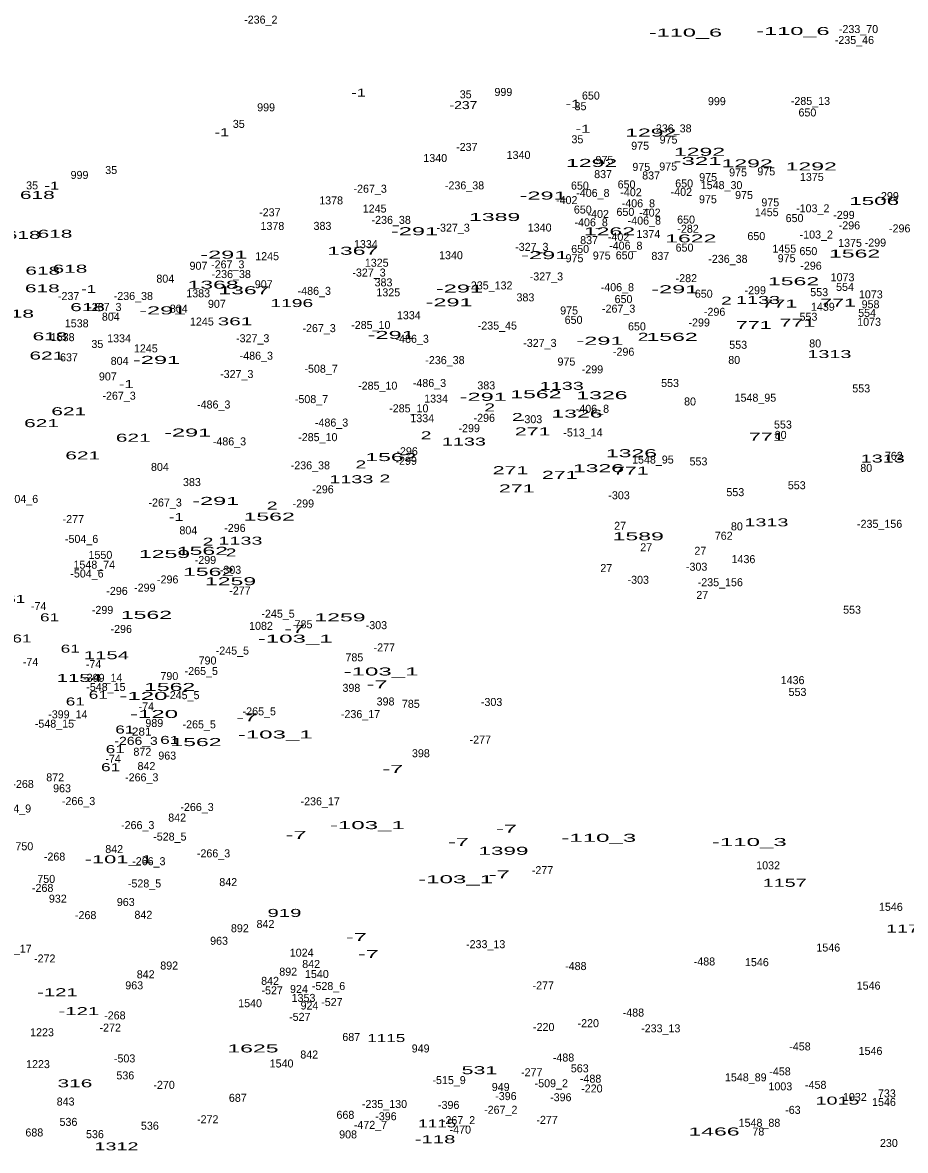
# Model space of a CAD drawing. Extents: x -660434 to -656144, y -997850 to -994016.
# Drawn here: x -658131 to -657690, y -996650 to -996086 of the extents above; entities that cross this region are included whole.
import ezdxf
from ezdxf.enums import TextEntityAlignment as Align

# ---------------------------------------------------------------- set-up
doc = ezdxf.new("R2010")
doc.units = 0
doc.header["$LTSCALE"] = 1.6
doc.layers.add('24', color=7, linetype='Continuous')

msp = doc.modelspace()

# ---------------------------------------------------------------- texts
at = {"layer": '24'}
for s, p in [('-236_2', (-658012.228, -996086.57)), ('-233_70', (-657713.311, -996091.3)), ('-235_46', (-657715.371, -996096.78)), ('35', (-657909.757, -996123.92)), ('999', (-657890.913, -996122.74)), ('650', (-657847.157, -996124.54)), ('999', (-658009.573, -996130.42)), ('35', (-657852.347, -996129.88)), ('999', (-657784.153, -996127.35)), ('-285_13', (-657737.355, -996127.24)), ('650', (-657738.867, -996132.99)), ('35', (-658023.237, -996138.71)), ('-236_38', (-657806.607, -996140.95)), ('35', (-657853.887, -996146.4)), ('975', (-657808.308, -996146.56)), ('-237', (-657909.211, -996150.24)), ('1340', (-657883.328, -996154.22)), ('975', (-657822.518, -996149.64)), ('1340', (-657924.988, -996155.76)), ('975', (-657840.378, -996156.74)), ('975', (-657821.938, -996160.2)), ('975', (-657808.498, -996160.01)), ('999', (-658102.883, -996164.23)), ('35', (-658087.047, -996161.76)), ('837', (-657841.043, -996163.82)), ('837', (-657817.033, -996164.49)), ('975', (-657788.518, -996165.33)), ('975', (-657773.548, -996162.93)), ('975', (-657759.428, -996162.45)), ('1375', (-657736.656, -996165.23)), ('35', (-658126.597, -996169.45)), ('-267_3', (-657957.534, -996171.12)), ('-236_38', (-657910.337, -996169.45)), ('650', (-657852.637, -996169.54)), ('650', (-657829.307, -996168.96)), ('650', (-657800.507, -996168.48)), ('1548_30', (-657781.796, -996169.31)), ('1378', (-657977.056, -996176.96)), ('-402', (-657859.223, -996176.81)), ('-406_8', (-657846.156, -996173.23)), ('-402', (-657827.083, -996172.88)), ('-402', (-657801.903, -996172.68)), ('975', (-657788.618, -996176.38)), ('975', (-657770.568, -996174.27)), ('-299', (-657698.515, -996174.8)), ('1245', (-657955.294, -996181.03)), ('650', (-657851.197, -996181.54)), ('650', (-657829.877, -996182.7)), ('-406_8', (-657823.406, -996178.41)), ('975', (-657757.418, -996177.92)), ('-103_2', (-657736.19, -996180.93)), ('-237', (-658007.711, -996182.9)), ('-236_38', (-657947.017, -996186.7)), ('-406_8', (-657847.026, -996187.92)), ('-402', (-657843.473, -996183.73)), ('-406_8', (-657820.426, -996187.06)), ('-402', (-657817.653, -996183.06)), ('650', (-657799.547, -996186.54)), ('1455', (-657759.204, -996182.84)), ('650', (-657745.297, -996185.81)), ('-299', (-657720.605, -996184.21)), ('1378', (-658006.426, -996189.73)), ('383', (-657981.387, -996189.7)), ('-327_3', (-657916.048, -996190.59)), ('1340', (-657872.758, -996190.52)), ('1374', (-657818.4, -996193.75)), ('-282', (-657798.555, -996191.13)), ('-103_2', (-657734.44, -996194.02)), ('-296', (-657717.865, -996189.43)), ('-296', (-657692.705, -996190.95)), ('1334', (-657959.694, -996198.83)), ('837', (-657848.043, -996196.82)), ('-402', (-657833.303, -996195.16)), ('-406_8', (-657829.696, -996199.59)), ('650', (-657764.407, -996194.8)), ('1375', (-657717.546, -996198.17)), ('-299', (-657704.865, -996198.04)), ('1245', (-658009.054, -996204.84)), ('1340', (-657917.118, -996204.35)), ('-327_3', (-657876.688, -996200.18)), ('650', (-657852.527, -996201.23)), ('975', (-657841.718, -996204.52)), ('650', (-657830.267, -996204.4)), ('837', (-657812.433, -996204.7)), ('650', (-657800.307, -996200.56)), ('1455', (-657750.394, -996201.06)), ('650', (-657738.387, -996202.33)), ('907', (-658043.402, -996209.64)), ('-267_3', (-658028.764, -996208.94)), ('1325', (-657954.25, -996208.12)), ('975', (-657855.348, -996205.86)), ('-236_38', (-657778.627, -996206.18)), ('975', (-657749.258, -996205.86)), ('-296', (-657737.065, -996209.6)), ('804', (-658059.985, -996216.08)), ('-236_38', (-658027.007, -996213.78)), ('-327_3', (-657958.098, -996213.02)), ('-327_3', (-657869.398, -996214.97)), ('-282', (-657799.415, -996215.82)), ('1073', (-657721.28, -996215.37)), ('907', (-658010.762, -996218.86)), ('-486_3', (-657985.472, -996222.18)), ('383', (-657950.857, -996217.94)), ('-235_132', (-657897.665, -996219.45)), ('-406_8', (-657833.916, -996220.34)), ('-299', (-657764.955, -996221.86)), ('554', (-657720.061, -996220.2)), ('-237', (-658108.321, -996224.77)), ('-236_38', (-658075.967, -996224.73)), ('1383', (-658043.55, -996223.42)), ('1325', (-657948.48, -996222.92)), ('383', (-657879.887, -996225.43)), ('650', (-657830.837, -996226.3)), ('650', (-657790.707, -996223.61)), ('553', (-657732.967, -996222.82)), ('1073', (-657707.16, -996223.92)), ('-267_3', (-658090.214, -996230.22)), ('804', (-658053.265, -996231.06)), ('907', (-658034.192, -996228.66)), ('975', (-657858.038, -996231.98)), ('-267_3', (-657833.264, -996231.07)), ('-296', (-657785.265, -996232.64)), ('1439', (-657731.15, -996230.13)), ('554', (-657709.021, -996233.17)), ('958', (-657707.283, -996228.87)), ('1538', (-658104.29, -996238.4)), ('804', (-658087.245, -996235.1)), ('1245', (-658041.694, -996237.5)), ('-285_10', (-657957.219, -996239.23)), ('1334', (-657938.194, -996234.36)), ('650', (-657855.797, -996236.67)), ('-299', (-657792.995, -996237.99)), ('553', (-657738.347, -996235.12)), ('1073', (-657708.02, -996237.66)), ('-267_3', (-657983.074, -996240.82)), ('-235_45', (-657893.926, -996239.52)), ('650', (-657824.117, -996239.93)), ('1538', (-658111.3, -996245.32)), ('35', (-658093.957, -996248.72)), ('1334', (-658083.104, -996245.89)), ('-327_3', (-658016.278, -996245.86)), ('-486_3', (-657936.512, -996246.14)), ('-327_3', (-657872.648, -996248.21)), ('553', (-657773.477, -996249.14)), ('80', (-657734.971, -996248.46)), ('637', (-658108.158, -996255.39)), ('1245', (-658069.724, -996250.94)), ('-486_3', (-658014.462, -996254.6)), ('-296', (-657830.765, -996252.62)), ('804', (-658082.835, -996257.19)), ('-508_7', (-657982.072, -996261.11)), ('-236_38', (-657920.127, -996256.8)), ('975', (-657859.378, -996257.53)), ('-299', (-657846.375, -996261.42)), ('80', (-657775.481, -996256.72)), ('907', (-658088.722, -996264.96)), ('-327_3', (-658024.248, -996263.76)), ('-285_10', (-657953.759, -996269.57)), ('-486_3', (-657927.872, -996268.23)), ('383', (-657899.467, -996269.42)), ('553', (-657807.557, -996268.25)), ('553', (-657711.947, -996270.94)), ('-267_3', (-658083.104, -996274.59)), ('-508_7', (-657986.872, -996276.29)), ('1334', (-657924.564, -996276.04)), ('80', (-657797.571, -996277.47)), ('1548_95', (-657764.877, -996275.58)), ('-486_3', (-658035.772, -996278.99)), ('-285_10', (-657938.209, -996280.91)), ('-406_8', (-657846.396, -996281.14)), ('-486_3', (-657976.832, -996288.02)), ('1334', (-657931.474, -996285.84)), ('-296', (-657900.465, -996285.65)), ('-303', (-657876.839, -996286.33)), ('553', (-657751.107, -996289)), ('-285_10', (-657983.709, -996295.31)), ('-299', (-657908.005, -996290.82)), ('-513_14', (-657851.133, -996292.98)), ('80', (-657752.251, -996294.19)), ('-486_3', (-658027.902, -996297.43)), ('-296', (-657939.065, -996302.36)), ('1548_95', (-657816.137, -996306.51)), ('762', (-657695.668, -996304.65)), ('804', (-658062.675, -996310.2)), ('-236_38', (-657987.447, -996309.39)), ('-299', (-657939.495, -996307.14)), ('553', (-657793.357, -996307.44)), ('80', (-657709.431, -996310.7)), ('383', (-658046.667, -996317.77)), ('-296', (-657981.115, -996321.38)), ('553', (-657774.917, -996322.8)), ('553', (-657744.197, -996319.35)), ('-504_6', (-658131.886, -996326.2)), ('-267_3', (-658060.064, -996327.99)), ('-299', (-657990.945, -996328.46)), ('-303', (-657833.059, -996324.36)), ('-277', (-658105.975, -996336.26)), ('-296', (-658025.185, -996340.69)), ('27', (-657832.543, -996339.62)), ('80', (-657774.141, -996339.89)), ('-235_156', (-657702.751, -996338.64)), ('-504_6', (-658101.846, -996346.18)), ('804', (-658048.465, -996341.89)), ('762', (-657780.728, -996344.6)), ('27', (-657819.493, -996350.37)), ('1550', (-658092.434, -996354.16)), ('-299', (-658039.915, -996356.7)), ('27', (-657792.413, -996352.1)), ('1436', (-657770.85, -996356.29)), ('1548_74', (-658095.492, -996359.05)), ('-303', (-658027.369, -996361.63)), ('27', (-657839.453, -996360.75)), ('-303', (-657794.269, -996360.09)), ('-504_6', (-658099.156, -996363.47)), ('-296', (-658058.785, -996366.43)), ('-303', (-657823.459, -996366.62)), ('-235_156', (-657782.431, -996367.84)), ('-296', (-658084.135, -996372.19)), ('-299', (-658070.245, -996370.53)), ('-277', (-658022.645, -996371.99)), ('27', (-657791.453, -996374.19)), ('-74', (-658123.335, -996379.78)), ('-299', (-658091.365, -996381.67)), ('-245_5', (-658003.597, -996383.57)), ('553', (-657716.547, -996381.58)), ('-296', (-658082.015, -996391.2)), ('1082', (-658012.124, -996389.64)), ('785', (-657990.863, -996388.86)), ('-303', (-657954.409, -996389.29)), ('-245_5', (-658026.447, -996402.01)), ('-277', (-657950.445, -996400.42)), ('-74', (-658127.365, -996407.64)), ('790', (-658038.852, -996406.96)), ('785', (-657965.423, -996405.37)), ('-74', (-658095.875, -996408.79)), ('-265_5', (-658041.988, -996412.2)), ('-399_14', (-658091.25, -996415.63)), ('790', (-658057.952, -996414.74)), ('1436', (-657746.27, -996416.79)), ('-548_15', (-658089.699, -996420.2)), ('-245_5', (-658051.207, -996424.29)), ('398', (-657966.923, -996420.63)), ('553', (-657743.817, -996422.68)), ('-74', (-658069.485, -996429.92)), ('398', (-657949.833, -996427.45)), ('785', (-657937.203, -996428.62)), ('-303', (-657896.809, -996427.7)), ('-399_14', (-658108.73, -996433.88)), ('-265_5', (-658012.978, -996432.37)), ('-236_17', (-657962.366, -996433.76)), ('-548_15', (-658115.429, -996438.54)), ('989', (-658065.488, -996438.2)), ('-265_5', (-658043.028, -996438.89)), ('-277', (-657902.455, -996446.52)), ('872', (-658071.463, -996452.59)), ('398', (-657932.173, -996453.33)), ('-74', (-658086.085, -996456.04)), ('963', (-658059.018, -996454.5)), ('842', (-658069.411, -996459.75)), ('-268', (-658131.11, -996468.69)), ('872', (-658115.053, -996465.36)), ('-266_3', (-658071.773, -996465.37)), ('963', (-658111.628, -996470.84)), ('-504_9', (-658135.416, -996480.96)), ('-266_3', (-658103.353, -996477.25)), ('-266_3', (-658044.113, -996480.22)), ('-236_17', (-657982.526, -996477.36)), ('842', (-658054.051, -996485.49)), ('-266_3', (-658073.783, -996489.26)), ('-528_5', (-658057.702, -996494.99)), ('750', (-658130.477, -996499.83)), ('842', (-658085.541, -996501.24)), ('-266_3', (-658035.863, -996503.38)), ('-268', (-658115.36, -996504.99)), ('-266_3', (-658068.213, -996507.31)), ('1032', (-657758.534, -996509.37)), ('-277', (-657871.345, -996511.78)), ('-268', (-658121.31, -996520.66)), ('750', (-658119.527, -996516.15)), ('-528_5', (-658070.372, -996518.42)), ('842', (-658028.511, -996517.75)), ('932', (-658113.733, -996526.02)), ('963', (-658079.758, -996527.7)), ('1546', (-657697.12, -996530.11)), ('-268', (-658099.81, -996534.25)), ('842', (-658070.951, -996534.08)), ('892', (-658022.703, -996540.81)), ('842', (-658009.891, -996538.69)), ('963', (-658033.098, -996547.08)), ('-233_13', (-657899.765, -996548.78)), ('-548_17', (-658136.635, -996551.04)), ('1024', (-657991.788, -996553.02)), ('1546', (-657728.42, -996550.47)), ('-272', (-658120.271, -996555.93)), ('892', (-658058.033, -996559.45)), ('842', (-657987.041, -996558.67)), ('-488', (-657854.689, -996559.73)), ('-488', (-657790.369, -996557.43)), ('1546', (-657764.13, -996557.77)), ('842', (-658069.791, -996563.85)), ('892', (-657998.513, -996562.52)), ('1540', (-657984.178, -996563.68)), ('963', (-658075.528, -996569.36)), ('842', (-658007.591, -996567.12)), ('-527', (-658006.541, -996571.86)), ('924', (-657993.147, -996571.18)), ('-528_6', (-657978.348, -996569.7)), ('-277', (-657870.965, -996569.4)), ('1546', (-657708.26, -996569.49)), ('1353', (-657990.86, -996575.64)), ('1540', (-658017.578, -996578.28)), ('924', (-657987.867, -996579.44)), ('-527', (-657976.681, -996577.71)), ('-488', (-657825.889, -996582.97)), ('-268', (-658085.22, -996584.38)), ('-527', (-657992.711, -996585.11)), ('-220', (-657848.469, -996588.27)), ('1223', (-658121.64, -996592.81)), ('-272', (-658087.531, -996590.5)), ('-220', (-657870.739, -996590.19)), ('-233_13', (-657812.215, -996590.85)), ('687', (-657966.988, -996595.18)), ('-458', (-657742.589, -996599.89)), ('842', (-657988.001, -996603.94)), ('949', (-657932.293, -996600.9)), ('-488', (-657860.829, -996605.44)), ('1546', (-657707.3, -996602.14)), ('1223', (-658123.66, -996608.75)), ('-503', (-658080.339, -996605.89)), ('1540', (-658001.838, -996608.43)), ('563', (-657852.723, -996610.84)), ('536', (-658079.983, -996614.38)), ('-515_9', (-657918.062, -996616.73)), ('-277', (-657876.725, -996612.81)), ('-488', (-657847.289, -996616.01)), ('1548_89', (-657769.687, -996615.34)), ('-458', (-657752.569, -996612.38)), ('-270', (-658060.584, -996619.11)), ('949', (-657892.253, -996620.19)), ('-509_2', (-657866.962, -996618.31)), ('-220', (-657846.649, -996620.92)), ('1003', (-657752.408, -996619.85)), ('-458', (-657734.719, -996619.1)), ('843', (-658109.831, -996627.45)), ('687', (-658023.728, -996625.59)), ('-396', (-657889.645, -996624.73)), ('-396', (-657862.185, -996625.3)), ('1032', (-657715.144, -996625.19)), ('1546', (-657700.58, -996627.68)), ('733', (-657699.123, -996623.39)), ('-235_130', (-657950.379, -996628.67)), ('-396', (-657918.255, -996629.14)), ('-267_2', (-657892.234, -996631.56)), ('-63', (-657746.12, -996631.61)), ('536', (-658108.413, -996637.62)), ('536', (-658067.703, -996639.54)), ('-272', (-658038.761, -996636.31)), ('668', (-657969.918, -996634.08)), ('-472_7', (-657957.388, -996639.1)), ('-396', (-657949.645, -996634.81)), ('-267_2', (-657913.354, -996636.76)), ('-277', (-657869.045, -996636.6)), ('1548_88', (-657762.842, -996638.07)), ('688', (-658125.483, -996642.91)), ('536', (-658095.163, -996643.76)), ('908', (-657968.577, -996643.88)), ('-470', (-657912.449, -996641.48)), ('78', (-657763.393, -996642.43)), ('230', (-657698.131, -996648.17))]:
    msp.add_text(s, height=4, dxfattribs=at).set_placement(p, align=Align.CENTER)
for s, width, p in [('-110_6', 2.2, (-657746.099, -996092.28)), ('-110_6', 2.2, (-657799.859, -996093.05)), ('-1', 1.55, (-657963.341, -996123.09)), ('-237', 1.3, (-657910.88, -996129.31)), ('-1', 1.55, (-657856.101, -996128.66)), ('-1', 1.55, (-658031.691, -996142.88)), ('-1', 1.55, (-657851.111, -996141.15)), ('1292', 2.15, (-657817.213, -996143.05)), ('1292', 2.15, (-657792.833, -996152.65)), ('1292', 2.15, (-657846.783, -996158.22)), ('-321', 2.25, (-657793.801, -996157.21)), ('1292', 2.15, (-657769.023, -996158.42)), ('1292', 2.15, (-657736.953, -996159.95)), ('-1', 1.55, (-658116.751, -996169.58)), ('618', 1.95, (-658123.973, -996174.22)), ('-291', 2.2, (-657871.035, -996174.54)), ('1506', 2.1, (-657705.469, -996177.24)), ('1389', 2.15, (-657895.273, -996185.26)), ('618', 1.95, (-658115.143, -996193.62)), ('-291', 2.2, (-657935.355, -996192.36)), ('1262', 2.15, (-657837.873, -996192.43)), ('618', 1.95, (-658131.073, -996194.2)), ('1622', 2.15, (-657797.193, -996195.95)), ('-291', 2.2, (-658030.725, -996204.08)), ('1367', 2.15, (-657966.267, -996202.14)), ('-291', 2.2, (-657870.265, -996204.31)), ('1562', 2.15, (-657715.253, -996203.54)), ('618', 1.95, (-658121.283, -996212.06)), ('618', 1.95, (-658107.653, -996211.1)), ('618', 1.95, (-658121.473, -996220.89)), ('-1', 1.55, (-658098.321, -996221.24)), ('1368', 2.15, (-658036.073, -996219.11)), ('1367', 2.15, (-658020.647, -996221.87)), ('-291', 2.2, (-657912.885, -996221.02)), ('-291', 2.2, (-657805.205, -996221.37)), ('1562', 2.15, (-657745.783, -996217.37)), ('-291', 2.2, (-657918.075, -996227.9)), ('2', 1.8, (-657779.361, -996227.07)), ('1133', 1.85, (-657763.544, -996226.72)), ('618', 1.95, (-658134.343, -996233.57)), ('618', 1.95, (-658098.823, -996230.31)), ('-291', 2.2, (-658061.255, -996231.94)), ('1196', 1.8, (-657996.733, -996228.28)), ('771', 2, (-657752.847, -996228.5)), ('771', 2, (-657723.517, -996228.07)), ('361', 1.95, (-658025.133, -996237.4)), ('771', 2, (-657743.827, -996238.11)), ('-291', 2.2, (-657947.025, -996244.21)), ('771', 2, (-657765.717, -996239.26)), ('618', 1.95, (-658117.633, -996244.9)), ('-291', 2.2, (-657842.615, -996247.11)), ('2', 1.8, (-657821.031, -996245.13)), ('1562', 2.15, (-657806.533, -996245.17)), ('621', 1.95, (-658119.213, -996254.51)), ('1313', 1.85, (-657727.864, -996253.76)), ('-291', 2.2, (-658064.345, -996256.69)), ('-1', 1.55, (-658079.501, -996268.77)), ('1133', 1.85, (-657861.694, -996269.66)), ('-291', 2.2, (-657900.985, -996275.15)), ('1562', 2.15, (-657874.653, -996273.83)), ('1326', 2.15, (-657841.633, -996274.33)), ('621', 1.95, (-658108.263, -996282.36)), ('2', 1.8, (-657897.751, -996280.44)), ('1326', 2.15, (-657854.113, -996283.55)), ('621', 1.95, (-658121.893, -996288.31)), ('2', 1.8, (-657883.931, -996285.24)), ('621', 1.95, (-658076.023, -996295.6)), ('-291', 2.2, (-658048.795, -996293)), ('2', 1.8, (-657929.551, -996294.37)), ('271', 2, (-657876.283, -996292.43)), ('771', 2, (-657759.187, -996295.15)), ('1133', 1.85, (-657910.664, -996297.52)), ('621', 1.95, (-658101.273, -996304.43)), ('1562', 2.15, (-657947.153, -996305.27)), ('1326', 2.15, (-657826.853, -996303.33)), ('1313', 1.85, (-657701.174, -996306)), ('2', 1.8, (-657962.191, -996308.96)), ('271', 2, (-657887.333, -996311.82)), ('1326', 2.15, (-657843.363, -996310.82)), ('771', 2, (-657827.157, -996312.06)), ('1133', 1.85, (-657966.914, -996316.34)), ('2', 1.8, (-657950.171, -996315.98)), ('271', 2, (-657862.713, -996314.15)), ('271', 2, (-657884.233, -996320.94)), ('-291', 2.2, (-658034.775, -996327.19)), ('1562', 2.15, (-658008.023, -996335.04)), ('2', 1.8, (-658006.551, -996329.52)), ('-1', 1.55, (-658054.541, -996335.23)), ('1313', 1.85, (-657759.354, -996337.89)), ('1589', 2.15, (-657823.463, -996344.88)), ('2', 1.8, (-658038.611, -996347.57)), ('1133', 1.85, (-658022.404, -996347.07)), ('1259', 2.15, (-658060.373, -996353.7)), ('1562', 2.15, (-658041.433, -996352.14)), ('2', 1.8, (-658027.091, -996352.95)), ('1562', 2.15, (-658038.313, -996362.63)), ('1259', 2.15, (-658027.353, -996367.33)), ('61', 1.6, (-658134.753, -996376.17)), ('61', 1.6, (-658117.863, -996385.39)), ('1562', 2.15, (-658069.413, -996384.14)), ('1259', 2.15, (-657972.623, -996385.39)), ('-7', 2.2, (-657995.319, -996391.15)), ('61', 1.6, (-658131.683, -996395.96)), ('-103_1', 2.25, (-657995.004, -996396.04)), ('61', 1.6, (-658107.533, -996401.05)), ('1154', 1.9, (-658089.419, -996404.31)), ('-103_1', 2.25, (-657952.094, -996412.46)), ('1154', 1.9, (-658103.009, -996415.69)), ('-7', 2.2, (-657954.029, -996418.9)), ('61', 1.6, (-658093.483, -996424.1)), ('-120', 2.25, (-658070.927, -996424.67)), ('1562', 2.15, (-658057.803, -996420.19)), ('61', 1.6, (-658104.993, -996427.46)), ('-120', 2.25, (-658065.637, -996433.7)), ('-7', 2.2, (-658019.319, -996435.42)), ('61', 1.6, (-658080.223, -996441.48)), ('-266_3', 1.3, (-658074.58, -996447.13)), ('-281', 1.1, (-658072.76, -996442.49)), ('61', 1.6, (-658057.763, -996446.66)), ('1562', 2.15, (-658044.643, -996447.75)), ('-103_1', 2.25, (-658005.004, -996443.95)), ('61', 1.6, (-658085.023, -996451.27)), ('61', 1.6, (-658087.333, -996460.3)), ('-7', 2.2, (-657946.169, -996461.13)), ('-103_1', 2.25, (-657958.924, -996489.26)), ('-7', 2.2, (-657889.339, -996491.09)), ('-7', 2.2, (-657994.559, -996494.16)), ('-7', 2.2, (-657913.339, -996497.62)), ('-110_3', 2.25, (-657843.204, -996495.61)), ('-110_3', 2.25, (-657767.944, -996497.72)), ('1399', 2.1, (-657890.887, -996502.1)), ('-101_1', 2.05, (-658083.26, -996506.34)), ('-7', 2.2, (-657892.989, -996513.94)), ('-103_1', 2.25, (-657914.794, -996516.31)), ('1157', 1.85, (-657750.219, -996518.11)), ('919', 1.9, (-658000.397, -996533.16)), ('1179', 1.85, (-657688.513, -996540.95)), ('-7', 2.2, (-657964.409, -996545.25)), ('-7', 2.2, (-657958.459, -996553.7)), ('-121', 1.9, (-658113.917, -996572.79)), ('-121', 1.9, (-658103.217, -996582.25)), ('1115', 1.6, (-657949.49, -996595.72)), ('1625', 2.15, (-658016.143, -996600.91)), ('531', 2, (-657902.887, -996611.77)), ('316', 1.95, (-658105.183, -996618.32)), ('1015', 1.85, (-657723.8, -996626.98)), ('1115', 1.6, (-657924, -996638.39)), ('1466', 2.15, (-657785.563, -996642.43)), ('1312', 1.85, (-658084.404, -996649.84)), ('-118', 1.9, (-657925.067, -996646.3))]:
    msp.add_text(s, height=4, dxfattribs=dict(at, width=width)).set_placement(p, align=Align.CENTER)

doc.saveas('drawing.dxf')
